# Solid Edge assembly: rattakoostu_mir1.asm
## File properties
Author: Türk
Template: Iso Assembly.asm
Last saved by: Türk
Revision: 2
Application: Solid Edge
Username: Türk
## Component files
VlegR18_2_mir1.par
Rehv.par
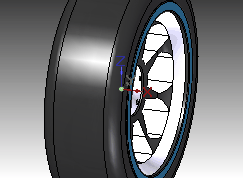
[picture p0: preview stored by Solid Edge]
